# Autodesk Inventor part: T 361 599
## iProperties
Company: Mayer & Müller AG Schaltgeräte
Created: 2006-01
Part Number: T 361 599
Material: Umabord KE
Document SubType Name: Modeling
Designer: I.Baliuc
Manufacturer: Standard
Standards Organization: Custom
Description: Schotung
Vendor: Fa. Gatex
Density: 0.94 g/cm^3
Zweck: Seitenteil rechts
Abmessung: 319 x 4 - 371
Author: T.Messerschmitt
Revision Number: 361599
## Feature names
1. Extrusion2
2. Bohrung_Ø35 [Hole]
3. Bohrung_Ø40 [Hole]
4. Bohrung_Ø3 [Hole]
